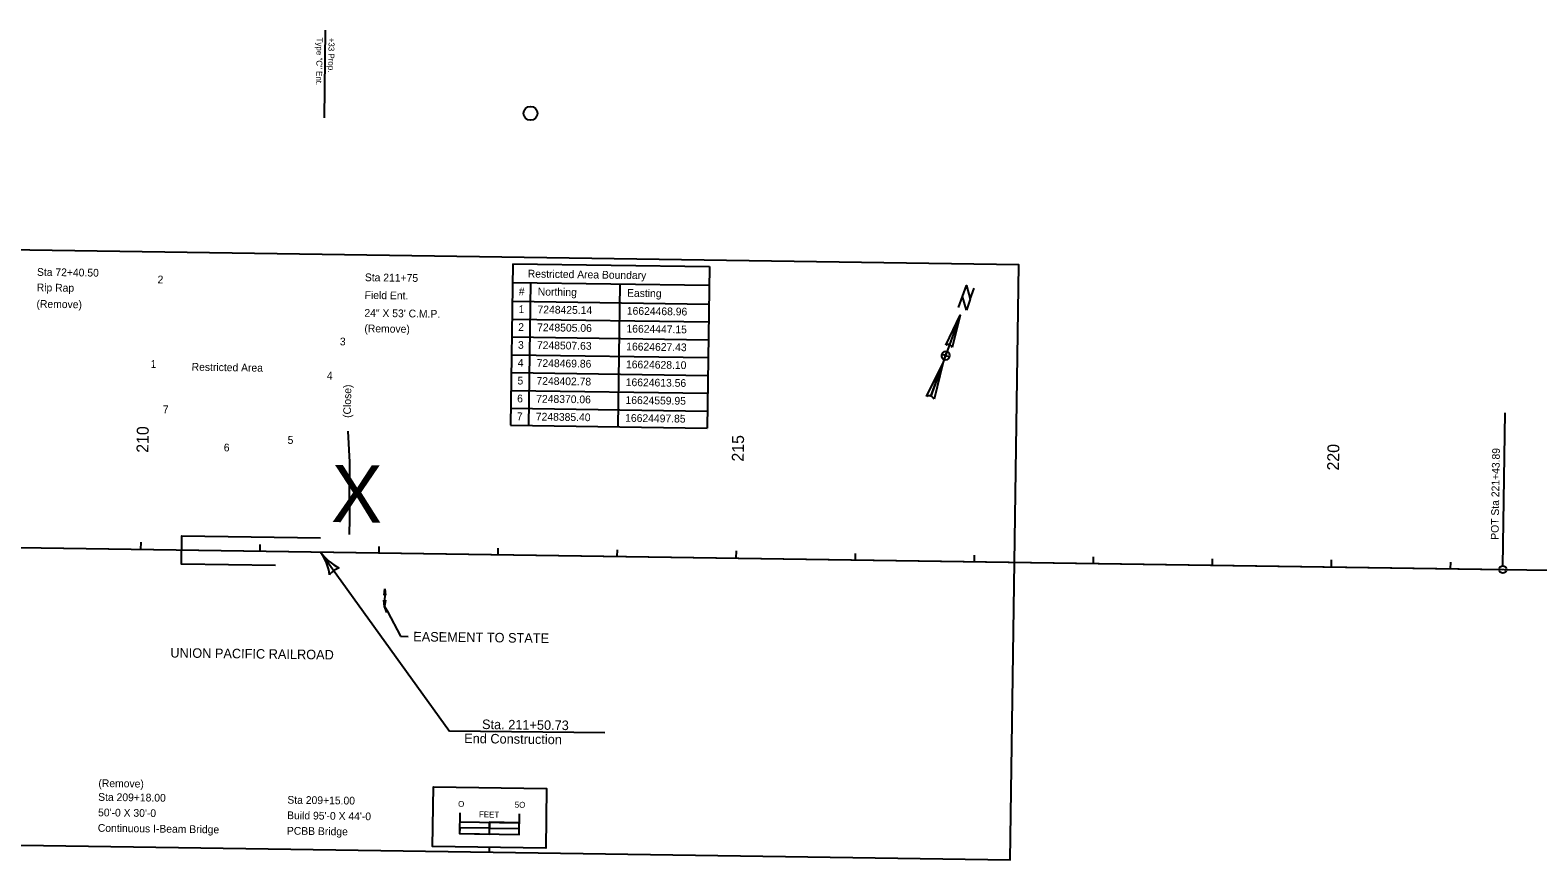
# Model space of a CAD drawing. Extents: x 14295116 to 14303545, y 8637313 to 8653417.
# Drawn here: x 14300829 to 14302096, y 8652720 to 8653417 of the extents above; entities that cross this region are included whole.
import ezdxf

# ---------------------------------------------------------------- set-up
doc = ezdxf.new("R2010")
doc.units = 0
for name, color, linetype in [('dsnCellElements', 7, 'Continuous'), ('dsnCellsNorthArrow', 7, 'Continuous'), ('dsnCellsScaleBlock', 7, 'Continuous'), ('dsnNonPlotable', 7, 'Continuous'), ('dsnProfileBarGraphArrows', 7, 'Continuous'), ('dsnProfileDitchGradePropLeft', 7, 'Continuous'), ('dsnProfileGradePropCircle', 7, 'Continuous'), ('dsnShtPortLev01', 7, 'Continuous'), ('dsnTextCulvertProp', 7, 'Continuous'), ('dsnTextEntranceProp', 7, 'Continuous'), ('dsnTextFinalPlan', 7, 'Continuous'), ('dsnTextProfileBarGraphLeft', 7, 'Continuous'), ('dsnTextProfileBarGraphRight', 7, 'Continuous'), ('dsnTextProfileGradeProp', 7, 'Continuous'), ('PhoNotesDesign', 7, 'Continuous'), ('phoTxtDrainage', 7, 'Continuous')]:
    doc.layers.add(name, color=color, linetype=linetype)

msp = doc.modelspace()

# ---------------------------------------------------------------- linework, layer by layer
at = {"layer": 'dsnCellElements'}
msp.add_lwpolyline([(14300092.5, 8653243.2), (14300085, 8652743.2), (14301652.4, 8652720), (14301659.8, 8653219.9)], close=True, dxfattribs=at)
at = {"layer": 'dsnCellsNorthArrow'}
for p, q in [((14301073.2, 8652978.6), (14301181.5, 8652828.2)), ((14301127, 8652932.8), (14301126.4, 8652938.1)), ((14301126.4, 8652938.1), (14301127.1, 8652937.6)), ((14301127, 8652932.8), (14301126.4, 8652938.1)), ((14301126.4, 8652938.1), (14301127.1, 8652937.6)), ((14301126.5, 8652942.5), (14301127.2, 8652947.8)), ((14301126.5, 8652942.5), (14301127.2, 8652947.8)), ((14301127.1, 8652943), (14301126.5, 8652942.5)), ((14301127.1, 8652943), (14301126.5, 8652942.5)), ((14301127, 8652933.5), (14301126.5, 8652938.1)), ((14301127, 8652933.5), (14301126.5, 8652938.1)), ((14301126.6, 8652942.6), (14301127.2, 8652947.1)), ((14301126.6, 8652942.6), (14301127.2, 8652947.1)), ((14301127, 8652934.1), (14301126.6, 8652938)), ((14301127, 8652934.1), (14301126.6, 8652938)), ((14301126.7, 8652942.6), (14301127.2, 8652946.5)), ((14301126.7, 8652942.6), (14301127.2, 8652946.5)), ((14301127, 8652934.8), (14301126.7, 8652937.9)), ((14301127, 8652934.8), (14301126.7, 8652937.9)), ((14301126.8, 8652942.7), (14301127.2, 8652945.8)), ((14301126.8, 8652942.7), (14301127.2, 8652945.8)), ((14301127, 8652935.5), (14301126.8, 8652937.8)), ((14301127, 8652935.5), (14301126.8, 8652937.8)), ((14301126.9, 8652942.8), (14301127.2, 8652945.1)), ((14301126.9, 8652942.8), (14301127.2, 8652945.1)), ((14301126.9, 8652942.9), (14301127.2, 8652944.5)), ((14301126.9, 8652942.9), (14301127.2, 8652944.5)), ((14301127, 8652936.2), (14301126.9, 8652937.8)), ((14301127, 8652936.2), (14301126.9, 8652937.8)), ((14301127.2, 8652947.8), (14301127, 8652932.8)), ((14301127, 8652942.9), (14301127.1, 8652943.8)), ((14301127, 8652942.9), (14301127.1, 8652943.8)), ((14301127.7, 8652938.1), (14301127, 8652932.8)), ((14301127.7, 8652938.1), (14301127, 8652932.8)), ((14301127.6, 8652938), (14301127, 8652933.5)), ((14301127.5, 8652938), (14301127, 8652934.1)), ((14301127.6, 8652938), (14301127, 8652933.5)), ((14301127.5, 8652938), (14301127, 8652934.1)), ((14301127.4, 8652937.9), (14301127, 8652934.8)), ((14301127.4, 8652937.9), (14301127, 8652934.8)), ((14301127.3, 8652937.8), (14301127, 8652935.5)), ((14301127.3, 8652937.8), (14301127, 8652935.5)), ((14301127.2, 8652937.7), (14301127, 8652936.2)), ((14301127.2, 8652937.7), (14301127, 8652936.8)), ((14301127, 8652936.8), (14301127, 8652937.7)), ((14301127.2, 8652937.7), (14301127, 8652936.2)), ((14301127.2, 8652937.7), (14301127, 8652936.8)), ((14301127, 8652936.8), (14301127, 8652937.7)), ((14301127.1, 8652937.6), (14301127, 8652932.8)), ((14301127.1, 8652937.6), (14301127, 8652932.8)), ((14301127.1, 8652943), (14301127.2, 8652947.8)), ((14301127.1, 8652943), (14301127.2, 8652947.8)), ((14301127.1, 8652943.8), (14301127.2, 8652942.9)), ((14301127.1, 8652943.8), (14301127.2, 8652942.9)), ((14301127.8, 8652942.5), (14301127.1, 8652943)), ((14301127.8, 8652942.5), (14301127.1, 8652943)), ((14301127.1, 8652937.6), (14301127.7, 8652938.1)), ((14301127.1, 8652937.6), (14301127.7, 8652938.1)), ((14301127.2, 8652947.8), (14301127.8, 8652942.5)), ((14301127.2, 8652947.8), (14301127.8, 8652942.5)), ((14301127.2, 8652947.1), (14301127.7, 8652942.6)), ((14301127.2, 8652947.1), (14301127.7, 8652942.6)), ((14301127.2, 8652946.5), (14301127.6, 8652942.6)), ((14301127.2, 8652946.5), (14301127.6, 8652942.6)), ((14301127.2, 8652945.8), (14301127.5, 8652942.7)), ((14301127.2, 8652945.8), (14301127.5, 8652942.7)), ((14301127.2, 8652945.1), (14301127.4, 8652942.8)), ((14301127.2, 8652945.1), (14301127.4, 8652942.8)), ((14301127.2, 8652944.5), (14301127.3, 8652942.9)), ((14301127.2, 8652944.5), (14301127.3, 8652942.9)), ((14301128.9, 8652927.8), (14301127, 8652932.8)), ((14301127, 8652932.8), (14301130.1, 8652928.4)), ((14301129.3, 8652928.6), (14301127, 8652932.8)), ((14301128.9, 8652927.8), (14301127, 8652932.8)), ((14301127, 8652932.8), (14301130.1, 8652928.4)), ((14301129.3, 8652928.6), (14301127, 8652932.8)), ((14301129, 8652927.9), (14301127.3, 8652932.2)), ((14301127.3, 8652932.2), (14301130, 8652928.5)), ((14301129, 8652927.9), (14301127.3, 8652932.2)), ((14301127.3, 8652932.2), (14301130, 8652928.5)), ((14301129, 8652928), (14301127.6, 8652931.6)), ((14301127.6, 8652931.6), (14301129.8, 8652928.5)), ((14301129, 8652928), (14301127.6, 8652931.6)), ((14301127.6, 8652931.6), (14301129.8, 8652928.5)), ((14301129.1, 8652928.1), (14301127.9, 8652931)), ((14301127.9, 8652931), (14301129.7, 8652928.5)), ((14301129.1, 8652928.1), (14301127.9, 8652931)), ((14301127.9, 8652931), (14301129.7, 8652928.5)), ((14301129.1, 8652928.3), (14301128.3, 8652930.4)), ((14301128.3, 8652930.4), (14301129.6, 8652928.5)), ((14301129.1, 8652928.3), (14301128.3, 8652930.4)), ((14301128.3, 8652930.4), (14301129.6, 8652928.5)), ((14301129.2, 8652928.4), (14301128.6, 8652929.9)), ((14301128.6, 8652929.9), (14301129.5, 8652928.5)), ((14301129.2, 8652928.4), (14301128.6, 8652929.9)), ((14301128.6, 8652929.9), (14301129.5, 8652928.5)), ((14301129.2, 8652928.5), (14301128.9, 8652929.3)), ((14301128.9, 8652929.3), (14301129.4, 8652928.6)), ((14301129.2, 8652928.5), (14301128.9, 8652929.3)), ((14301128.9, 8652929.3), (14301129.4, 8652928.6)), ((14301129.3, 8652928.6), (14301128.9, 8652927.8)), ((14301129.3, 8652928.6), (14301128.9, 8652927.8)), ((14301130.1, 8652928.4), (14301129.3, 8652928.6)), ((14301130.1, 8652928.4), (14301129.3, 8652928.6)), ((14301140.4, 8652907.8), (14301146.8, 8652907.7)), ((14301311.9, 8652826.6), (14301181.5, 8652828.2))]:
    msp.add_line(p, q, dxfattribs=at)
msp.add_lwpolyline([(14301127, 8652932.8), (14301129.3, 8652928.6), (14301140.4, 8652907.8)], dxfattribs=at)
for centre, radius, start, end in [((14301107.6, 8653003.5), 42.5, 215.7635, 243.836), ((14301038.7, 8652953.8), 42.5, 7.691, 35.7635), ((14301094, 8652949.7), 16.4, 108.0302, 143.4969)]:
    msp.add_arc(centre, radius, start, end, dxfattribs=at)
at = {"layer": 'dsnCellsScaleBlock'}
msp.add_line((14301215, 8652741.6), (14301215.1, 8652751.6), dxfattribs=at)
msp.add_line((14301215, 8652741.6), (14301215.1, 8652751.6), dxfattribs=at)
for points in [[(14301167.3, 8652731.3), (14301168.1, 8652781.3), (14301263.1, 8652779.9), (14301262.3, 8652729.9)], [(14301190, 8652742), (14301215, 8652741.6), (14301215.1, 8652746.6), (14301190.1, 8652747)], [(14301215.1, 8652746.6), (14301240.1, 8652746.3), (14301240.1, 8652751.2), (14301215.1, 8652751.6)]]:
    msp.add_lwpolyline(points, close=True, dxfattribs=at)
for points in [[(14301190.3, 8652759.5), (14301190, 8652742), (14301240, 8652741.2), (14301240.3, 8652758.7)], [(14301190.1, 8652752), (14301240.1, 8652751.2)]]:
    msp.add_lwpolyline(points, dxfattribs=at)
at = {"layer": 'dsnProfileDitchGradePropLeft'}
msp.add_line((14301076.4, 8653343.5), (14301077.5, 8653417.1), dxfattribs=at)
at = {"layer": 'dsnProfileGradePropCircle'}
msp.add_line((14302066.3, 8652967), (14302068.2, 8653095.5), dxfattribs=at)
msp.add_circle((14302066.2, 8652963.9), 3.13, dxfattribs=at)
at = {"layer": 'dsnShtPortLev01'}
msp.add_line((14299285.9, 8653005.1), (14302066.2, 8652963.9), dxfattribs=at)
at = {"layer": 'dsnTextCulvertProp'}
msp.add_lwpolyline([(14301035.5, 8652967.2), (14300956.3, 8652968.3), (14300956.6, 8652992.3), (14301073.3, 8652990.6)], dxfattribs=at)
at = {"layer": 'dsnTextEntranceProp'}
msp.add_lwpolyline([(14301097.4, 8652993.3), (14301097.7, 8653006.5), (14301097.6, 8653029), (14301097.9, 8653054.2), (14301096.4, 8653080.1)], dxfattribs=at)
at = {"layer": 'dsnTextFinalPlan'}
for p, q in [((14301610.4, 8653177.7), (14301585.9, 8653109.5)), ((14301610.4, 8653177.7), (14301603.6, 8653150.6)), ((14301598.4, 8653152.4), (14301598.4, 8653152.4)), ((14301598.6, 8653152.7), (14301599.2, 8653153)), ((14301597, 8653140.4), (14301597, 8653140.4)), ((14301582.2, 8653109.4), (14301595.8, 8653137.1))]:
    msp.add_line(p, q, dxfattribs=at)
for points in [[(14301609, 8653184.2), (14301615.6, 8653202.5), (14301618.9, 8653191), (14301622.2, 8653200.2)], [(14301598.4, 8653152.4), (14301610.4, 8653177.7), (14301601.5, 8653152.8)], [(14301597, 8653140.4), (14301598.2, 8653143.6), (14301594.9, 8653144.8)], [(14301601.4, 8653142.5), (14301598.2, 8653143.6), (14301599.3, 8653146.9)], [(14301585.9, 8653109.5), (14301595.8, 8653137.1), (14301588.7, 8653107)]]:
    msp.add_lwpolyline(points, dxfattribs=at)
for points in [[(14301615.6, 8653181.8), (14301612.3, 8653193.4), (14301615.6, 8653202.5), (14301618.9, 8653191)], [(14301168.1, 8652781.3), (14301263.1, 8652779.9), (14301262.3, 8652729.9), (14301167.3, 8652731.3)], [(14301168.1, 8652781.3), (14301263.1, 8652779.9), (14301262.3, 8652729.9), (14301167.3, 8652731.3)]]:
    msp.add_lwpolyline(points, close=True, dxfattribs=at)
for centre, radius, start, end in [((14301600.3, 8653149.5), 3.49, 70.2625, 123.3678), ((14301600.3, 8653149.5), 3.48, 17.0901, 70.2639), ((14301598.2, 8653143.6), 3.48, 160.2421, 250.2421), ((14301598.2, 8653143.6), 3.48, 70.2421, 160.2421), ((14301598.2, 8653143.6), 3.49, 250.2421, 340.2421), ((14301598.2, 8653143.6), 3.49, 340.2421, 70.2421), ((14301584.2, 8653104.8), 5.05, 70.2315, 113.861), ((14301584.2, 8653104.8), 5.05, 26.6441, 70.2427)]:
    msp.add_arc(centre, radius, start, end, dxfattribs=at)
at = {"layer": 'dsnTextProfileGradeProp'}
for p, q in [((14300922.4, 8652980.8), (14300922.5, 8652987)), ((14301022.4, 8652979.4), (14301022.5, 8652984.9)), ((14301122.4, 8652977.9), (14301122.5, 8652983.4)), ((14301222.4, 8652976.4), (14301222.5, 8652981.9)), ((14301322.4, 8652974.9), (14301322.5, 8652980.4)), ((14301422.4, 8652973.4), (14301422.5, 8652979.5)), ((14301522.4, 8652971.9), (14301522.5, 8652977.4)), ((14301622.4, 8652970.5), (14301622.5, 8652976)), ((14301722.4, 8652969), (14301722.4, 8652974.5)), ((14301822.4, 8652967.5), (14301822.4, 8652973)), ((14301922.4, 8652966), (14301922.4, 8652972.1)), ((14302022.3, 8652964.5), (14302022.4, 8652970))]:
    msp.add_line(p, q, dxfattribs=at)
at = {"layer": 'PhoNotesDesign'}
for p, q in [((14299285.9, 8653005.1), (14303544.9, 8652941.9)), ((14301214.8, 8652730.6), (14301214.8, 8652726.5))]:
    msp.add_line(p, q, dxfattribs=at)
at = {"layer": 'phoTxtDrainage'}
for p, q in [((14301234.8, 8653220.9), (14301232.8, 8653085.2)), ((14301234.8, 8653220.9), (14301399.8, 8653218.5)), ((14301399.8, 8653218.5), (14301397.8, 8653082.7)), ((14301234.5, 8653205.2), (14301399.5, 8653202.7)), ((14301249.5, 8653205), (14301247.8, 8653085)), ((14301324.5, 8653203.8), (14301322.8, 8653083.9)), ((14301234.3, 8653189.4), (14301399.3, 8653187)), ((14301234.1, 8653174.4), (14301399.1, 8653172)), ((14301233.9, 8653159.4), (14301398.9, 8653157)), ((14301233.6, 8653144.4), (14301398.6, 8653142)), ((14301233.4, 8653129.4), (14301398.4, 8653127)), ((14301233.2, 8653114.4), (14301398.2, 8653112)), ((14301233, 8653099.4), (14301398, 8653097)), ((14301232.8, 8653085.2), (14301397.8, 8653082.7))]:
    msp.add_line(p, q, dxfattribs=at)
msp.add_circle((14301249.5, 8653347.2), 5.86, dxfattribs=at)

# ---------------------------------------------------------------- texts
at = {"layer": 'dsnCellsNorthArrow'}
for s, p in [('EASEMENT TO STATE', (14301151, 8652903.6)), ('UNION PACIFIC RAILROAD', (14300947, 8652890)), ('Sta. 211+50.73', (14301208.8, 8652829.9)), ('End Construction', (14301193.8, 8652818.1))]:
    msp.add_text(s, height=8, rotation=359.2807, dxfattribs=at).set_placement(p)
at = {"layer": 'dsnCellsScaleBlock'}
for s, p in [('O', (14301188.7, 8652764.5)), ('FEET', (14301206.2, 8652755.7)), ('5O', (14301236.3, 8652763.8))]:
    msp.add_text(s, height=5, rotation=359.1493, dxfattribs=at).set_placement(p)
at = {"layer": 'dsnNonPlotable'}
for s, p in [('210', (14300928.6, 8653061.9)), ('215', (14301428.6, 8653054.5)), ('220', (14301928.6, 8653047))]:
    msp.add_text(s, height=10, rotation=89.1493, dxfattribs=at).set_placement(p)
at = {"layer": 'dsnProfileBarGraphArrows'}
for s, height, rotation, p in [('Sta 72+40.50', 6.5, 359.2287, (14300835, 8653210.7)), ('Rip Rap', 6.5, 359.2287, (14300834.8, 8653197.7)), ('(Remove)', 6.5, 359.2287, (14300834.6, 8653183.9)), ('(Close)', 6.5, 89.2807, (14301098.7, 8653091.3)), ('X', 48.1, 359.2287, (14301081.9, 8653003.8))]:
    msp.add_text(s, height=height, rotation=rotation, dxfattribs=at).set_placement(p)
at = {"layer": 'dsnProfileDitchGradePropLeft'}
for s, p in [('Type "C" Ent.', (14301070, 8653410.9)), ('+33 Prop.', (14301080, 8653410.8))]:
    msp.add_text(s, height=5, rotation=269.1628, dxfattribs=at).set_placement(p)
at = {"layer": 'dsnProfileGradePropCircle'}
msp.add_text('POT Sta 221+43.89', height=6.5, rotation=89.1493, dxfattribs=at).set_placement((14302062.6, 8652988.9))
at = {"layer": 'dsnTextProfileBarGraphLeft'}
for s, p in [('Sta 211+75', (14301110.4, 8653206.2)), ('Field Ent.', (14301110.2, 8653191.3)), ('24" X 53\' C.M.P.', (14301110, 8653176.3)), ('Sta 209+18.00', (14300886.4, 8652769.6)), ("50'-0 X 30'-0", (14300886.3, 8652756.6)), ('Continuous I-Beam Bridge', (14300886.1, 8652743.6))]:
    msp.add_text(s, height=6.5, rotation=359.2287, dxfattribs=at).set_placement(p)
at = {"layer": 'dsnTextProfileBarGraphRight'}
for s, p in [('(Remove)', (14301110, 8653163.3)), ('(Remove)', (14300886.6, 8652781.2)), ('Sta 209+15.00', (14301045.3, 8652767.2)), ("Build 95'-0 X 44'-0", (14301045.1, 8652754.2)), ('PCBB Bridge', (14301044.9, 8652741.2))]:
    msp.add_text(s, height=6.5, rotation=359.2287, dxfattribs=at).set_placement(p)
at = {"layer": 'phoTxtDrainage'}
for s, p in [('Restricted Area Boundary', (14301247.2, 8653209.3)), ('2', (14300936.3, 8653204.4)), ('#', (14301239.7, 8653194.4)), ('Northing', (14301255.6, 8653194.2)), ('Easting', (14301330.6, 8653193.1)), ('1', (14301239.5, 8653179.4)), ('7248425.14', (14301255.4, 8653179.2)), ('16624468.96', (14301330.4, 8653178.1)), ('2', (14301239.2, 8653164.4)), ('7248505.06', (14301255.1, 8653164.2)), ('16624447.15', (14301330.1, 8653163.1)), ('3', (14301089.4, 8653152.3)), ('3', (14301239, 8653149.4)), ('7248507.63', (14301254.9, 8653149.2)), ('16624627.43', (14301329.9, 8653148.1)), ('1', (14300930.4, 8653133.4)), ('4', (14301238.8, 8653134.4)), ('7248469.86', (14301254.7, 8653134.2)), ('16624628.10', (14301329.7, 8653133.1)), ('Restricted Area', (14300964.9, 8653131)), ('4', (14301078.5, 8653123.6)), ('5', (14301238.6, 8653119.4)), ('7248402.78', (14301254.5, 8653119.2)), ('16624613.56', (14301329.5, 8653118.1)), ('7', (14300940.7, 8653095.3)), ('6', (14301238.3, 8653104.4)), ('7248370.06', (14301254.3, 8653104.2)), ('16624559.95', (14301329.3, 8653103.1)), ('7', (14301238.1, 8653089.4)), ('7248385.40', (14301254, 8653089.2)), ('16624497.85', (14301329, 8653088.1)), ('5', (14301045.5, 8653069.5)), ('6', (14300991.9, 8653063.2))]:
    msp.add_text(s, height=6.5, rotation=359.1493, dxfattribs=at).set_placement(p)

doc.saveas('drawing.dxf')
